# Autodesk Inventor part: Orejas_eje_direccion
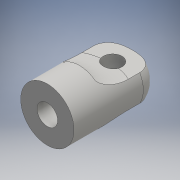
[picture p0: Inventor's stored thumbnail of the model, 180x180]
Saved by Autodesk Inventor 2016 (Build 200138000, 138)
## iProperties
Created: 2017-06
Part Number: Orejas_eje_direccion
Material: Generic
Document SubType Name: Modeling
Designer: laboratorioesan
Density: 1 g/cm^3
Appearance: Default
Author: laboratorioesan
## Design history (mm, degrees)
sketch "Sketch1"
  geometry: C1 r 3.85 at (0, 0); C2 r 10 at (0, 0); 1 further point
  constraints: 2 centre point, 2 coincident
  dimensions: "d0" = 7.7 diameter of C1; "d1" = 20 diameter of C2
extrude "Extrusion1" new body sketch "Sketch1" distance "d2" = 12; taper "d3" = 0 deg
sketch "Sketch2"
  geometry: C1 r 3.85 at (0, 0) reference; C2 r 10 at (0, 0) reference; 1 further point
extrude "Extrusion2" join sketch "Sketch2" distance "d4" = 20; taper "d5" = 0 deg
sketch "Sketch3"
  geometry: L1 (-8.66, 5)-(8.66, 5); L2 (8.66, -5)-(-8.66, -5); C1 r 10 at (0, 0) reference; A1 r 10 centre (0, 0) between (-8.66, 5) and (-8.66, -5); A2 r 10 centre (0, 0) between (8.66, -5) and (8.66, 5); 2 further points
  constraints: 4 end point, 4 point on circle, 2 centre point, 1 coincident, 1 horizontal, 1 midpoint, 1 parallel, 1 vertical alignment
  dimensions: "d8" = 20 diameter of C1 (derived); "d9" = 10 distance between parallel lines of L2 L1
extrude "Extrusion3" cut sketch "Sketch3" distance "d10" = 20; taper "d11" = 0 deg
sketch "Sketch4"
  geometry: L1 (0, 0)-(17.321, 0) reference; L2 (0, -20)-(0, 0) reference; L3 (0, -20)-(17.321, -20) reference; L4 (17.321, 0)-(17.321, -20) reference; C1 r 3.5 at (8.66, -7.5); 1 further point
  constraints: 1 centre point
  dimensions: "d12" = 7 diameter of C1; "d13" = 7.5 distance from line of L1 C1.centre
extrude "Extrusion4" cut sketch "Sketch4" distance "d14" = 15; taper "d15" = 0 deg
fillet "Fillet1" dims "d16" = 16
fillet "Fillet2" dims "d17" = 16
fillet "Fillet3" dims "d18" = 6
body "Solid1"
node "Projected Loop1"
node "Projected Loop2"
node "Projected Loop3"
